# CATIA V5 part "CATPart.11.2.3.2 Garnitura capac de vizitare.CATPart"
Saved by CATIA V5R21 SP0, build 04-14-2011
Part number: Capac de vizitare
Bounding box of the stored display mesh (mm): x 0 to 62, y 0 to 78.844, z -0.75 to 0.75
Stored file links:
  C:\Users\MIRCEA\Desktop\MOM\Mogan\model\CATPart.11.2.3.2 Garnitura capac de vizitare.CATPart
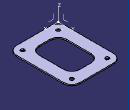
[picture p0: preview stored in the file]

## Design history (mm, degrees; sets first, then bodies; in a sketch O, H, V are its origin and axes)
Parameters
  L = 78.844 mm
  l = 62 mm
  R = 10 mm
  g = 1.5 mm
  h = 14 mm
  r = 10 mm
AxisSystem1: origin (0, 0, 0), X (1, 0, 0), Y (0, 1, 0), Z (0, 0, 1)
Body1 (main body)
  Sketch1 on xy-plane, origin (0, 0, 0), H (1, 0, 0), V (0, 1, 0)
    line L1 (10, 0) -> (52, 0)
    line L2 (62, 10) -> (62, 68.844)
    line L3 (52, 78.844) -> (10, 78.844)
    line L4 (0, 68.844) -> (0, 10)
    line L5 (24, 14) -> (38, 14)
    line L6 (48, 24) -> (48, 54.844)
    line L7 (38, 64.844) -> (24, 64.844)
    line L8 (14, 54.844) -> (14, 24)
    arc A1 centre (10, 68.844) radius 10 from (10, 78.844) to (0, 68.844) ccw
    arc A2 centre (24, 54.844) radius 10 from (14, 54.844) to (24, 64.844) cw
    arc A3 centre (24, 24) radius 10 from (14, 24) to (24, 14) ccw
    arc A4 centre (38, 24) radius 10 from (38, 14) to (48, 24) ccw
    arc A5 centre (38, 54.844) radius 10 from (38, 64.844) to (48, 54.844) cw
    arc A6 centre (52, 68.844) radius 10 from (52, 78.844) to (62, 68.844) cw
    arc A7 centre (52, 10) radius 10 from (62, 10) to (52, 0) cw
    arc A8 centre (10, 10) radius 10 from (10, 0) to (0, 10) cw
    radius A1 = 10 {= R}
    radius A2 = 10 {= r}
    radius A3 = 10 {= R}
    radius A4 = 10 {= r}
    radius A5 = 10 {= r}
    radius A6 = 10 {= R}
    radius A7 = 10 {= R}
    radius A8 = 10 {= R}
    distance L1 L3 = 78.844 {= L}
    distance L4 L2 = 62 {= l}
    distance L8 L4 = 14 {= h}
    distance L7 L3 = 14 {= h}
    distance L6 L2 = 14 {= h}
    distance L1 L5 = 14 {= h}
    horizontal: L1 H, L3 H, L5 H, L7 H
    vertical: L2 V, L4 V, L6 V, L8 V
    tangency: A1 L3, A1 L4, A2 L8, A2 L7, A3 L8, A3 L5, A4 L5, A4 L6, A5 L7, A5 L6, A6 L3, A6 L2, A7 L2, A7 L1, A8 L1, A8 L4
    coincidence: L1 O, L4 O
  Pad1: profile Sketch1, direction (0, 0, 1), length 0.75 {= g/2}, mirrored extent
  Sketch2 on start face of Pad1, origin (54, 9, -0.75), H (1, 0, 0), V (0, -1, 0)
    point P1 (-1, 0)
    reference projected point E1 (-1, 0) from Sketch4.P1
    coincidence: E1 P1
  Hole1: placed by Sketch2, at (53, 9, -0.75) direction (0, 0, 1), diameter 5, depth 10
  Sketch3 on start face of Pad1, origin (0, 0, -0.75), H (1, 0, 0), V (0, -1, 0)
    point P1 (9, -9)
    point P2 (9, -69.844)
    point P3 (53, -69.844)
    reference projected line E1 (62, -10) -> (62, -68.844) from edge [start face of Pad1 | face of Pad1 from Sketch1.L2]
    reference projected line E2 (52, -78.844) -> (10, -78.844) from edge [start face of Pad1 | face of Pad1 from Sketch1.L3]
    reference projected line E3 (0, -68.844) -> (0, -10) from edge [start face of Pad1 | face of Pad1 from Sketch1.L4]
    reference projected line E4 (52, -78.844) -> (10, -78.844) from edge [start face of Pad1 | face of Pad1 from Sketch1.L3]
    reference projected line E5 (10, 0) -> (52, 0) from edge [start face of Pad1 | face of Pad1 from Sketch1.L1]
    reference projected line E6 (0, -68.844) -> (0, -10) from edge [start face of Pad1 | face of Pad1 from Sketch1.L4]
    distance P3 E1 = 9
    distance P3 E2 = 9
    distance P2 E3 = 9
    distance P2 E4 = 9
    distance P1 E5 = 9
    distance P1 E6 = 9
  UserPattern1: of Hole1, copies 4, at the points of Sketch3
  Sketch4 on start face of Pad1, origin (0, 0, -0.75), H (1, 0, 0), V (0, -1, 0)
    point P1 (53, -9)
    reference projected line E1 (10, 0) -> (52, 0) from edge [start face of Pad1 | face of Pad1 from Sketch1.L1]
    reference projected line E2 (62, -10) -> (62, -68.844) from edge [start face of Pad1 | face of Pad1 from Sketch1.L2]
    distance P1 E1 = 9
    distance P1 E2 = 9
